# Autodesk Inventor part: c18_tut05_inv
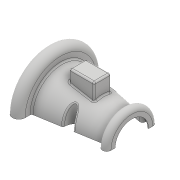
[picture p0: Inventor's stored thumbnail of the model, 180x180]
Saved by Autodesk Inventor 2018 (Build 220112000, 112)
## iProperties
Created: 2017-06
Part Number: c18_tut05_inv
Material: Generic
Document SubType Name: Modeling
Designer: CADCIM 00
Density: 1 g/cm^3
Appearance: Default
Author: CADCIM 00
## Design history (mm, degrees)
sketch "Sketch1"
  geometry: L1 (0, 30)-(0, 42.5); L2 (15, 42.5)-(15, 35); L3 (15, 35)-(90, 22.5); L4 (100, 25)-(100, 20); L5 (90, 25)-(90, 22.5); L6 (0, 0)-(90, 0); A1 r 7.5 centre (7.5, 42.5) between (15, 42.5) and (0, 42.5); A2 r 5 centre (95, 25) between (100, 25) and (90, 25)
  constraints: 12 end point, 4 point on circle, 4 tangent, 2 centre point, 2 parallel, 2 vertical, 2 vertical alignment, 1 horizontal
  dimensions: "d0" = 60 diameter of L1.start L6; "d1" = 70 diameter of L2.end L6; "d2" = 85 diameter of L1.end L6; "d3" = 100 distance between parallel lines of L4 L1; "d4" = 7.5 radius of A1; "d5" = 5 radius of A2; "d6" = 40 diameter of L4.end L6; "d7" = 45 diameter of L3.end L6; "d8" = 50 diameter of L4.start L6
feature "RevolutionSrf1" sketch "Sketch1" dims angle "d9" = 180 deg
sketch "Sketch2" dims "d10" = 5, "d11" = 10
  geometry: L1 (90, 22.5)-(15, 35) reference; 2 further points; 1 other entity
  constraints: 1 midpoint, 2 other
extrude_surface "ExtrusionSrf1" sketch "Sketch2" dims "d12" = 30, "d13" = 0
mirror "Mirror1"
feature "Trim3"
feature "Trim4"
feature "Trim5"
feature "Trim6"
workplane "Work Plane1"
sketch "Sketch3"
  geometry: L1 (35, 10)-(65, 10); L2 (65, 10)-(65, -10); L3 (65, -10)-(35, -10); L4 (35, -10)-(35, 10); 1 further point
  constraints: 8 end point, 2 parallel, 1 horizontal, 1 perpendicular
  dimensions: "d15" = 30 distance of L1.start L1.end; "d16" = 20 distance of L1.end L2.end; "d17" = 10 distance from line of point (0, 0) L3; "d18" = 35 distance from line of L4 point (0, 0)
split "Split1"
delete_face "Delete Face1"
sketch "3D Sketch1"
feature "Stitch Surface1"
fillet "Fillet1" dims "d25" = 2
thicken "Thicken1" dims "d26" = 1
body "Solid1"
body "Srf1"
body "Srf2"
body "Srf3"
node "Edges1"
body "Srf4"
body "Srf5"
body "Srf6"
extrude_surface "ExtrusionSrf2"
feature "LoftSrf1" dims "d19" = 0, "d20" = 90 deg, "d21" = 0, "d22" = 90 deg
patch "Boundary Patch1" dims "d23" = 5, "d24" = 0
other parameters: "d14" = 45
